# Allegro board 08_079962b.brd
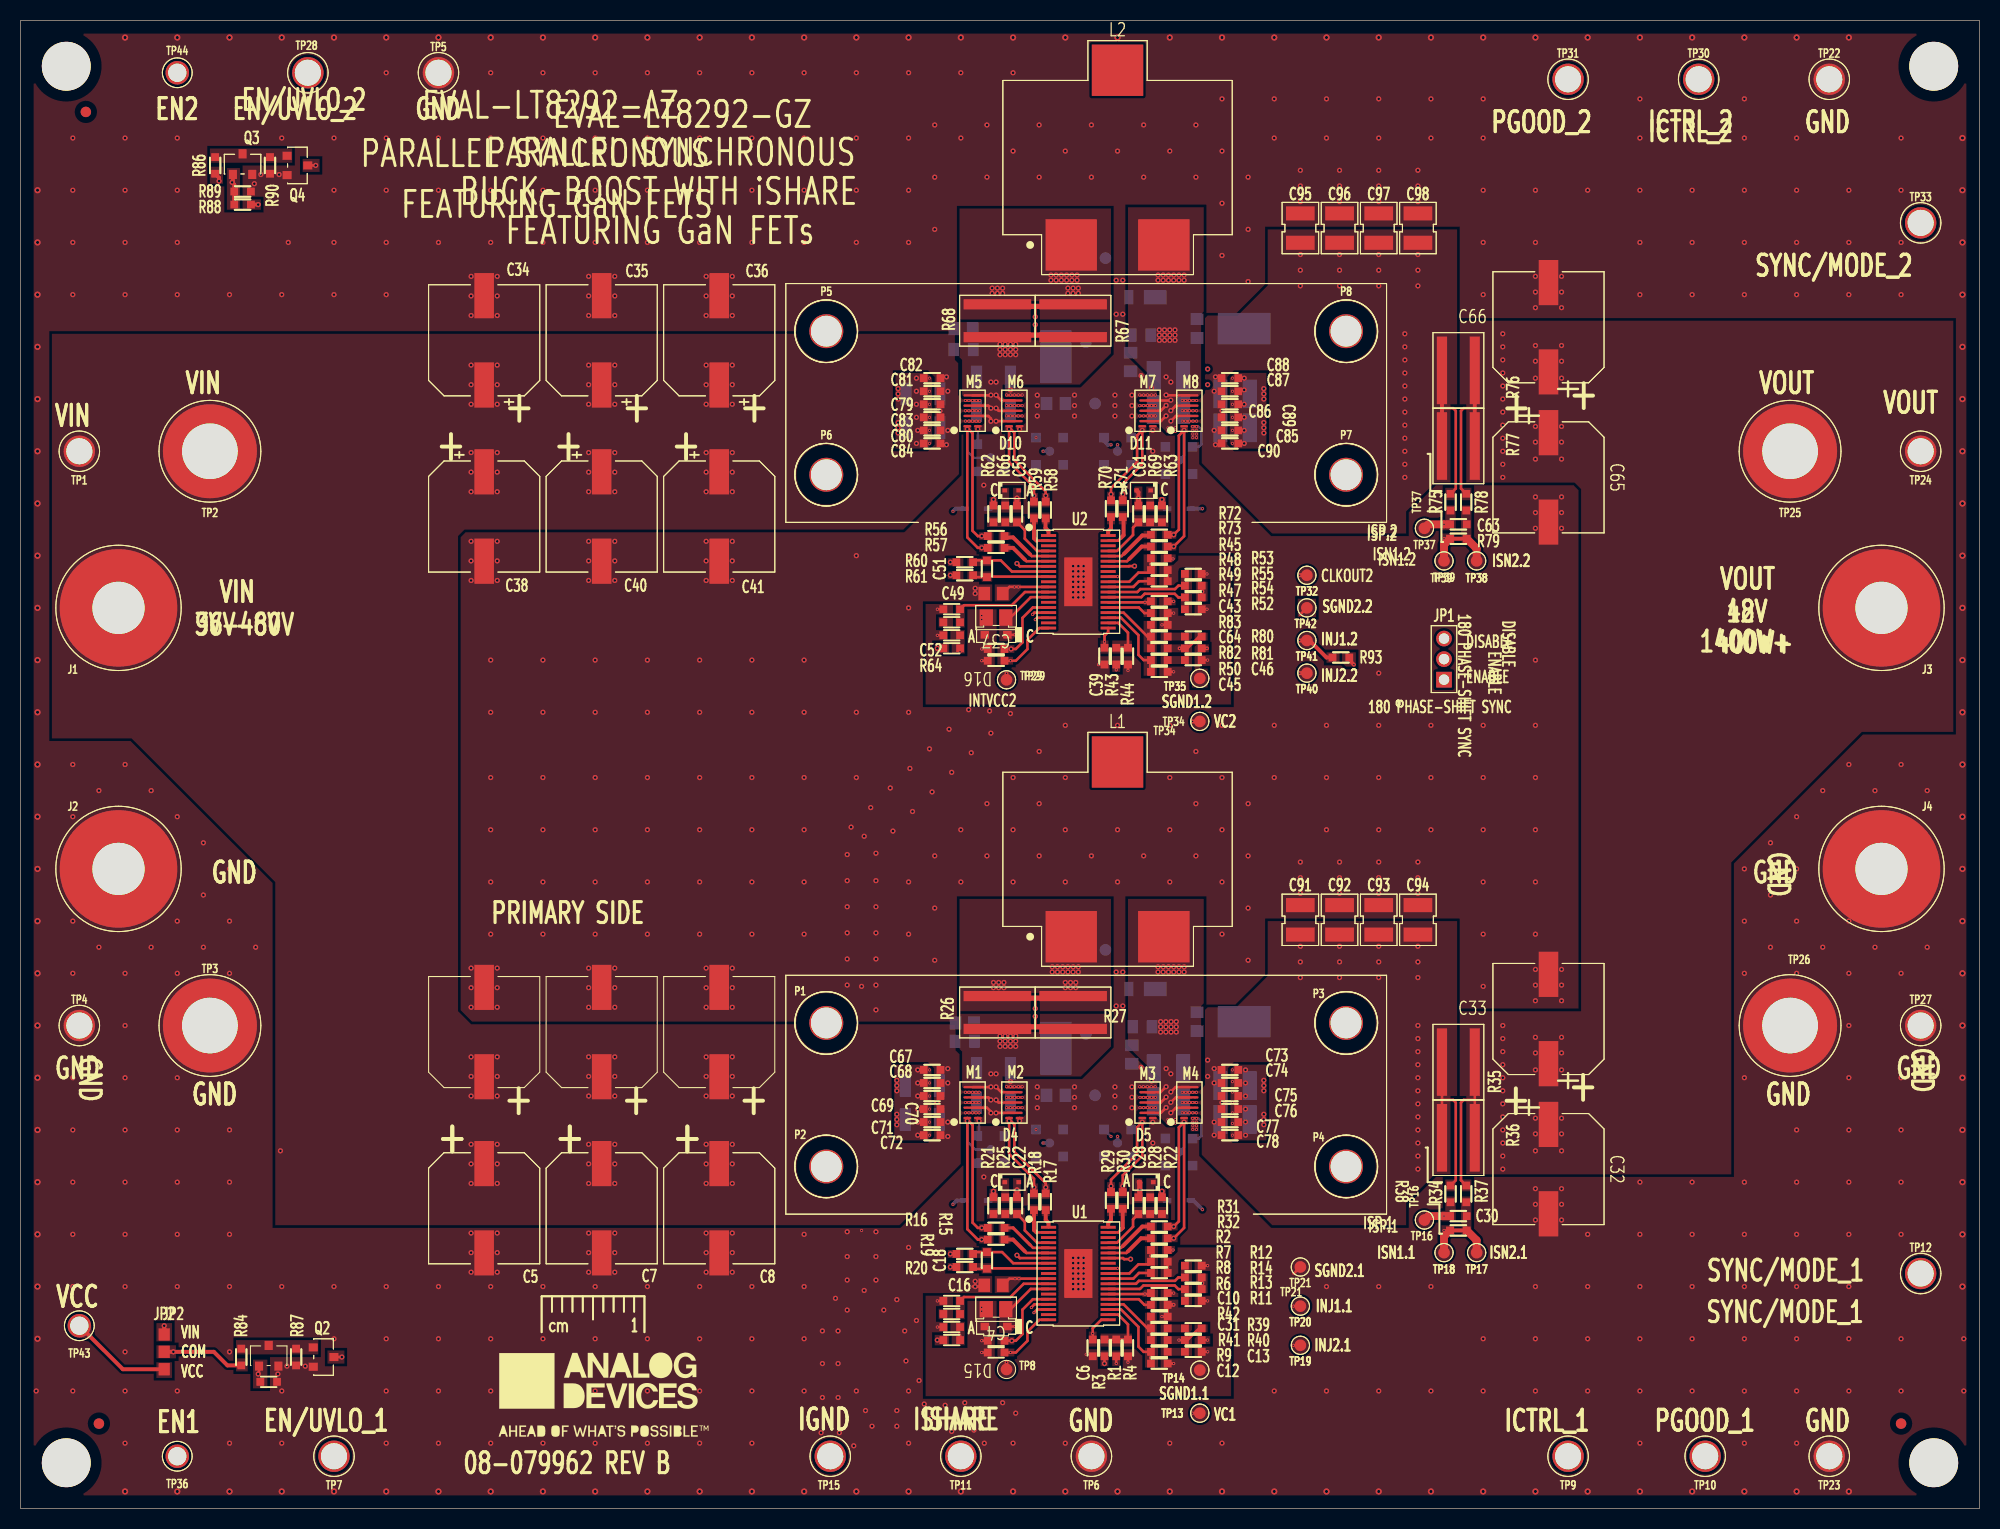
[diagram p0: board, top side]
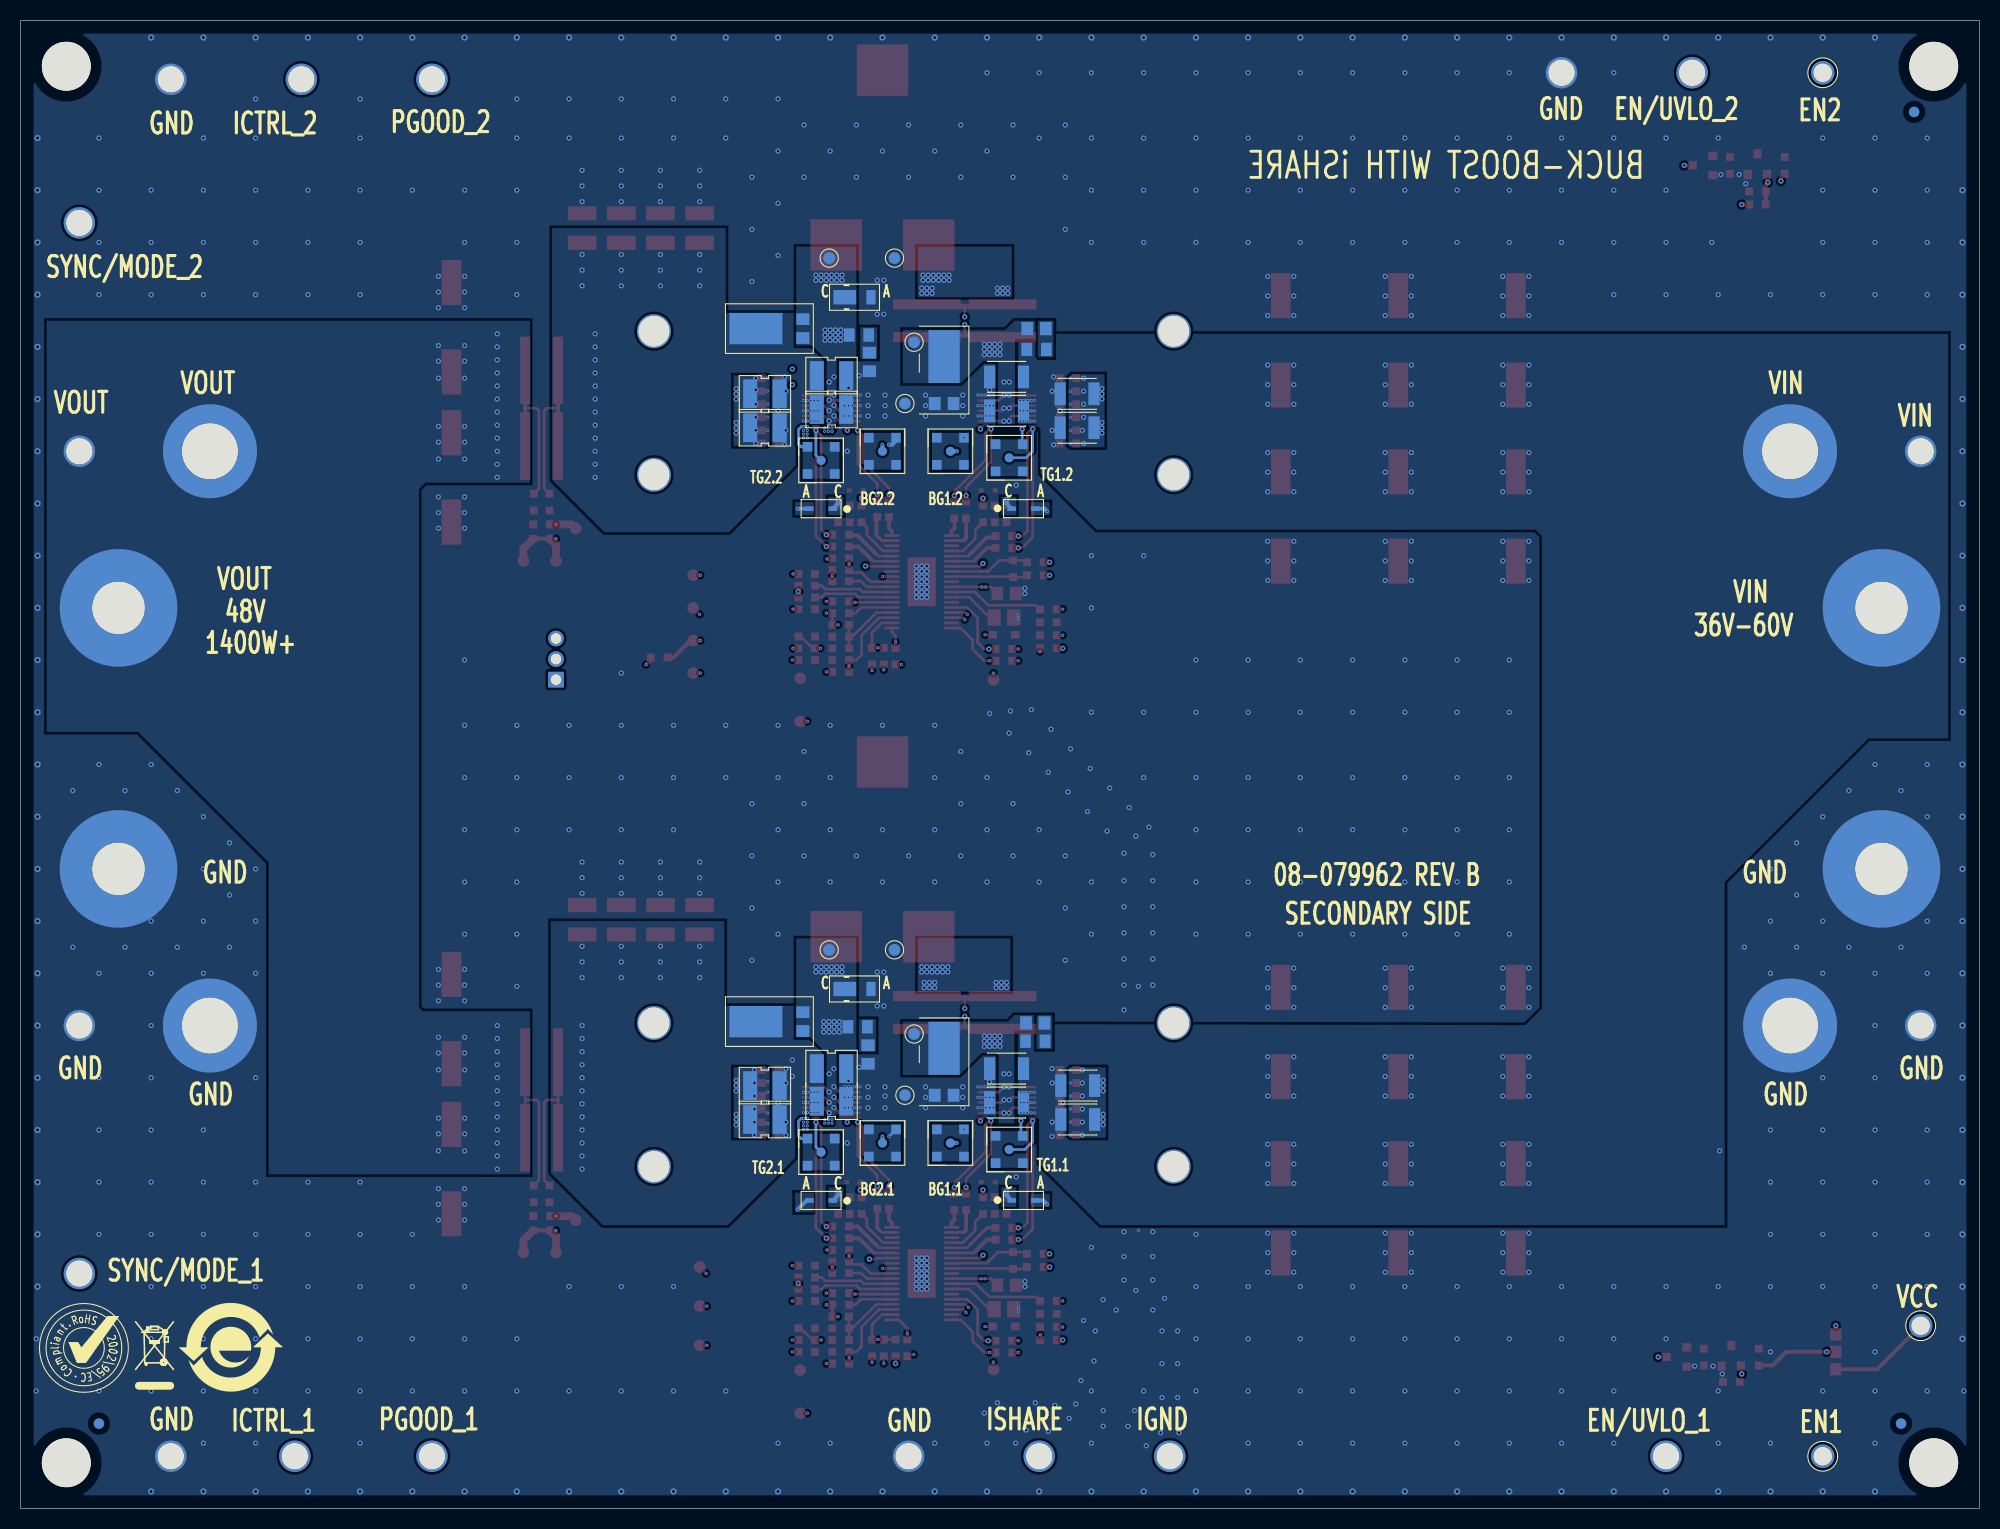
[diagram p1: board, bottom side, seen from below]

Outline 190.5 x 144.78 mm; copper layers: TOP, L2_GND, L3_SIG, L4_SIG, L5_GND, BOTTOM. Coordinates in mm from the lower left corner of the outline.
Outline path: 0,144.78 0,0 190.5,0 190.5,144.78 0,144.78

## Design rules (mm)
constraint set DEFAULT: min track width 0.254

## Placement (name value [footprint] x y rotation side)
C1  68UF  [CPLSMSQ406H500]  45.09 46.35 90 top
C2  68UF  [CPLSMSQ406H500]  56.52 46.35 90 top
C3  68UF  [CPLSMSQ406H500]  67.94 46.35 90 top
C4  10uF  [C0805H53]  94.87 19.38 180 top
C5  68UF  [CPLSMSQ406H500]  45.09 29.21 270 top
C6  TBD0603  [C0603]  104.27 15.62 270 top
C7  68UF  [CPLSMSQ406H500]  56.52 29.21 270 top
C8  68UF  [CPLSMSQ406H500]  67.94 29.21 270 top
C9  2200pF  [C0603]  90.55 20.19 0 top
C10  0.1uF  [C0603]  110.74 19.81 0 top
C11  4.7uF  [C1210H87]  94.62 39.5 0 bottom
C12  TBD0603  [C0603]  110.74 14.1 0 top
C13  6800PF  [C0603]  114.05 15.24 0 top
C14  4.7uF  [C1210H87]  94.62 42.8 0 bottom
C15  4.7uF  [C1210H87]  87.69 37.85 180 bottom
C16  1uF  [C0805]  94.62 21.72 180 top
C17  4.7uF  [C1210H87]  87.69 41.15 180 bottom
C18  1000pF  [C0603]  93.98 24.13 270 top
C19  1UF  [C0603]  94.87 16.32 180 top
C20  TBD0805  [C0805]  91.82 47.24 0 bottom
C21  10UF  [C1210H110]  111.63 42.8 180 bottom
C22  0.1uF  [C0603]  96.9 29.46 90 top
C23  10UF  [C1210H110]  111.63 39.62 180 bottom
C24  10UF  [C1210H110]  118.11 37.85 0 bottom
C25  10UF  [C1210H110]  118.11 41.15 0 bottom
C27  TBD0805  [C0805]  108.08 44.17 270 bottom
C28  0.1uF  [C0603]  108.71 29.46 90 top
C30  10uF  [C0603]  139.83 28.45 0 top
C31  TBD0603  [C0603]  110.74 17.53 180 top
C32  68UF  [CPLSMSQ406H500]  148.59 33.02 270 top
C33  68UF  [CPLSMSQ406H500]  148.59 47.62 90 top
C34  68UF  [CPLSMSQ406H500]  45.09 113.66 90 top
C35  68UF  [CPLSMSQ406H500]  56.52 113.66 90 top
C36  68UF  [CPLSMSQ406H500]  67.94 113.66 90 top
C37  10uF  [C0805H53]  94.87 86.69 180 top
C38  68UF  [CPLSMSQ406H500]  45.09 96.52 270 top
C39  TBD0603  [C0603]  105.41 82.93 270 top
C40  68UF  [CPLSMSQ406H500]  56.52 96.52 270 top
C41  68UF  [CPLSMSQ406H500]  67.94 96.52 270 top
C42  2200pF  [C0603]  90.55 87.5 0 top
C43  0.1uF  [C0603]  110.74 87.12 0 top
C44  4.7uF  [C1210H87]  94.62 110.11 0 bottom
C45  TBD0603  [C0603]  110.74 81.41 0 top
C46  6800PF  [C0603]  114.05 82.55 0 top
C47  4.7uF  [C1210H87]  87.76 108.46 180 bottom
C48  4.7uF  [C1210H87]  94.62 106.81 0 bottom
C49  1uF  [C0805]  94.62 89.03 180 top
C50  4.7uF  [C1210H87]  87.76 105.16 180 bottom
C51  1000pF  [C0603]  93.98 91.44 270 top
C52  1UF  [C0603]  94.87 83.63 180 top
C53  TBD0805  [C0805]  91.69 114.81 0 bottom
C54  10UF  [C1210H110]  111.63 106.93 180 bottom
C55  0.1uF  [C0603]  96.9 96.77 90 top
C56  10UF  [C1210H110]  111.63 110.24 180 bottom
C57  10UF  [C1210H110]  118.11 105.16 0 bottom
C58  10UF  [C1210H110]  118.11 108.46 0 bottom
C60  TBD0805  [C0805]  107.95 111.56 270 bottom
C61  0.1uF  [C0603]  108.71 96.77 90 top
C63  10uF  [C0603]  139.83 95.76 0 top
C64  TBD0603  [C0603]  110.74 84.84 180 top
C65  68UF  [CPLSMSQ406H500]  148.59 100.33 270 top
C66  68UF  [CPLSMSQ406H500]  148.59 114.94 90 top
C67  0.22UF  [C0603]  88.65 42.67 180 top
C68  0.22UF  [C0603]  88.65 41.4 180 top
C69  0.22UF  [C0603]  88.65 40.13 180 top
C70  0.22UF  [C0603]  88.65 38.86 180 top
C71  0.22UF  [C0603]  88.65 37.59 180 top
C72  0.22UF  [C0603]  88.65 36.32 180 top
C73  1UF  [C0603]  117.6 42.67 0 top
C74  1UF  [C0603]  117.6 41.4 0 top
C75  1UF  [C0603]  117.6 40.13 0 top
C76  1UF  [C0603]  117.6 38.86 0 top
C77  1UF  [C0603]  117.6 37.59 0 top
C78  1UF  [C0603]  117.6 36.32 0 top
C79  0.22UF  [C0603]  88.65 107.44 180 top
C80  0.22UF  [C0603]  88.65 104.9 180 top
C81  0.22UF  [C0603]  88.65 108.71 180 top
C82  0.22UF  [C0603]  88.65 109.98 180 top
C83  0.22UF  [C0603]  88.65 106.17 180 top
C84  0.22UF  [C0603]  88.65 103.63 180 top
C85  1UF  [C0603]  117.6 104.9 0 top
C86  1UF  [C0603]  117.6 106.17 0 top
C87  1UF  [C0603]  117.6 108.71 0 top
C88  1UF  [C0603]  117.6 109.98 0 top
C89  1UF  [C0603]  117.6 107.44 0 top
C90  1UF  [C0603]  117.6 103.63 0 top
C91  10UF  [C1210H110]  124.46 57.28 90 top
C92  10UF  [C1210H110]  128.27 57.28 90 top
C93  10UF  [C1210H110]  132.08 57.28 90 top
C94  10UF  [C1210H110]  135.89 57.28 90 top
C95  10UF  [C1210H110]  124.46 124.59 90 top
C96  10UF  [C1210H110]  128.27 124.59 90 top
C97  ZÁ  [C1210H110]  132.08 124.59 90 top
C98  10UF  [C1210H110]  135.89 124.59 90 top
D1  BAT46WJ,115  [SOD323F]  92.96 29.97 180 bottom
D2  BAT46WJ,115  [SOD323F]  112.65 29.97 0 bottom
D3  PDS3100-13  [POWERDI5]  100.69 43.46 180 bottom
D4  MM5Z5V1ST1G  [SOD523]  96.39 31.75 0 top
D5  MM5Z5V1ST1G  [SOD523]  109.47 31.75 180 top
D6  PDS3100-13  [POWERDI5]  117.68 47.37 90 bottom
D7  BAT46WJ,115  [SOD323F]  92.96 97.28 180 bottom
D8  BAT46WJ,115  [SOD323F]  112.65 97.28 0 bottom
D9  PDS3100-13  [POWERDI5]  100.69 110.77 180 bottom
D10  MM5Z5V1ST1G  [SOD523]  96.39 99.06 0 top
D11  MM5Z5V1ST1G  [SOD523]  109.22 99.06 180 top
D12  PDS3100-13  [POWERDI5]  117.68 114.81 90 bottom
D13  DFLS260-7  [POWERDI123]  109.4 50.55 180 bottom
D14  DFLS260-7  [POWERDI123]  109.4 117.86 180 bottom
D15  PLZ5V6A-G3/H  [DO219AC]  94.87 17.7 180 top
D16  PLZ5V6A-G3/H  [DO219AC]  94.87 85.01 180 top
J1  KFH-032-10ET  [CNPEMKFH-032]  9.53 87.63 0 top
J2  KFH-032-10ET  [CNPEMKFH-032]  9.53 62.23 0 top
J3  KFH-032-10ET  [CNPEMKFH-032]  180.97 87.63 0 top
J4  KFH-032-10ET  [CNPEMKFH-032]  180.97 62.23 0 top
J5  0734152063  [CNSMASQ136H203]  94.36 34.92 180 bottom
J6  0734152063  [CNSMASQ136H203]  100.08 35.56 180 bottom
J7  0734152063  [CNSMASQ136H203]  106.68 35.56 180 bottom
J8  0734152063  [CNSMASQ136H203]  112.65 34.67 180 bottom
J9  0734152063  [CNSMASQ136H203]  94.36 102.24 180 bottom
J10  0734152063  [CNSMASQ136H203]  100.08 102.87 180 bottom
J11  0734152063  [CNSMASQ136H203]  106.68 102.87 180 bottom
J12  0734152063  [CNSMASQ136H203]  112.65 101.98 180 bottom
JP1  TMM-103-02-L-S  [CNTHMHDR1X3L236W78H215]  138.43 80.65 90 top
JP2  3PINJUMPER0603  [JUMPER0603_3P]  13.97 15.24 90 top
L1  3.1UH  [LSML858W571H571]  106.68 64.13 0 top
L2  3.1UH  [LSML858W571H571]  106.68 131.44 0 top
M1  EPC2088  [DIE8_3_5X1_95_A]  92.58 39.5 90 top
M2  EPC2088  [DIE8_3_5X1_95_A]  96.65 39.5 90 top
M3  EPC2088  [DIE8_3_5X1_95_A]  109.6 39.5 90 top
M4  EPC2088  [DIE8_3_5X1_95_A]  113.66 39.5 90 top
M5  EPC2088  [DIE8_3_5X1_95_A]  92.58 106.81 90 top
M6  EPC2088  [DIE8_3_5X1_95_A]  96.65 106.81 90 top
M7  EPC2088  [DIE8_3_5X1_95_A]  109.6 106.81 90 top
M8  EPC2088  [DIE8_3_5X1_95_A]  113.66 106.81 90 top
NOREF  -  []  261.75 258.44 0 top
NOREF#2  -  []  10.29 147.7 0 top
NOREF#3  -  []  0 0 0 top
NOREF#4  -  []  190.5 0 90 top
NOREF#5  -  []  -34.73 322.66 0 top
NOREF#6  -  []  0 144.78 0 top
NOREF#7  -  []  -63.5 -69.85 0 top
NOREF#8  -  []  -209.55 -139.7 0 top
NOREF#9  -  []  190.5 0 90 top
NOREF#10  -  [unnamed#2]  6.35 135.89 0 top
NOREF#11  -  [unnamed#2]  4.45 4.45 180 top
NOREF#12  -  []  56.13 11.05 0 top
NOREF#13  VAL  []  103.63 107.57 0 top
NOREF#14  -  []  0 0 0 top
NOREF#15  -  [unnamed#2]  186.06 140.33 180 top
NOREF#16  -  []  0 0 0 top
NOREF#17  -  []  84.16 321.24 0 top
NOREF#18  -  []  -63.5 -69.85 0 top
NOREF#19  -  []  190.5 0 0 top
NOREF#20  -  []  4.45 4.45 0 top
NOREF#21  -  [unnamed#2]  186.06 4.45 180 top
NOREF#22  -  [unnamed#2]  4.45 140.33 180 top
NOREF#23  -  []  -53.12 239.13 0 top
NOREF#24  -  []  190.5 144.78 180 top
NOREF#25  -  []  -209.55 -139.7 0 top
NOREF#26  -  [unnamed#2]  182.88 8.26 0 top
NOREF#27  -  []  232.94 289.76 0 top
NOREF#28  -  [unnamed#2]  7.62 8.26 0 top
NOREF#29  -  []  102.62 150.37 0 top
NOREF#30  -  []  -63.5 -69.85 0 top
NOREF#31  -  []  50.67 17.14 0 top
NOREF#32  VAL  []  103.63 40.26 0 top
NOREF#33  -  []  4.45 4.45 0 top
NOREF#34  -  []  0 144.78 270 top
NOREF#35  -  []  70.89 219.1 0 top
NOREF#36  -  []  0 144.78 0 top
NOREF#37  -  [unnamed#2]  7.62 8.26 180 bottom
NOREF#38  -  []  184.34 15.62 180 bottom
NOREF#39  -  [unnamed#2]  182.88 8.26 180 bottom
NOREF#40  -  []  170.05 15.68 180 bottom
NOREF#41  -  [unnamed#2]  6.35 135.89 180 bottom
NOREF#42  -  []  177.67 11.62 180 bottom
P1  9774010243R  [CNWURTH9774010243R]  78.36 47.24 0 top
P2  9774010243R  [CNWURTH9774010243R]  78.36 33.27 0 top
P3  9774010243R  [CNWURTH9774010243R]  128.91 47.24 0 top
P4  9774010243R  [CNWURTH9774010243R]  128.91 33.27 0 top
P5  9774010243R  [CNWURTH9774010243R]  78.36 114.55 0 top
P6  9774010243R  [CNWURTH9774010243R]  78.36 100.58 0 top
P7  9774010243R  [CNWURTH9774010243R]  128.91 100.58 0 top
P8  9774010243R  [CNWURTH9774010243R]  128.91 114.55 0 top
Q1  BSS123-7-F  [SOT23-M3]  24.13 14.86 0 top
Q2  BSS123-7-F  [SOT23-M3]  29.46 14.73 270 top
Q3  BSS123-7-F  [SOT23-M3]  21.59 130.81 0 top
Q4  BSS123-7-F  [SOT23-M3]  26.92 130.68 270 top
R1  TBD0603  [R0603]  105.41 15.62 270 top
R2  TBD0603  [R0603]  110.74 25.15 180 top
R3  100K  [R0603]  106.55 15.62 90 top
R4  TBD0603  [R0603]  107.7 15.62 270 top
R5  18.7K  [R0603]  90.55 17.65 180 top
R6  100K  [R0603]  110.74 20.96 180 top
R7  TBD0603  [R0603]  110.74 24 0 top
R8  127K  [R0603]  110.74 22.91 0 top
R9  18.7K  [R0603]  110.74 15.24 0 top
R10  499K  [R0603]  90.55 16.38 0 top
R11  82K  [R0603]  114.05 20.19 0 top
R12  82K  [R0603]  114.05 23.62 0 top
R13  0  [R0603]  114.05 21.34 0 top
R14  0  [R0603]  114.05 22.48 0 top
R15  2  [R0603]  94.87 27.3 180 top
R16  1  [R0603]  94.87 26.16 180 top
R17  1  [R0603]  99.69 29.84 90 top
R18  2  [R0603]  98.55 29.84 90 top
R19  80.6  [R0603]  91.82 24.77 180 top
R20  80.6  [R0603]  91.82 23.5 180 top
R21  0  [R0603]  94.62 29.46 270 top
R22  0  [R0603]  111 29.46 270 top
R23  0  [R0603]  94.87 15.18 180 top
R24  TBD0805  [R0805]  91.82 45.47 180 bottom
R25  20  [R0603]  95.76 29.46 90 top
R26  0.003  [R1225H28]  95 48.26 90 top
R27  0.003  [R1225H28]  102.36 48.26 90 top
R28  20  [R0603]  109.85 29.46 90 top
R29  2  [R0603]  106.04 29.97 90 top
R30  1  [R0603]  107.19 29.97 90 top
R31  1  [R0603]  110.74 27.43 0 top
R32  2  [R0603]  110.74 26.29 0 top
R33  TBD0805  [R0805]  109.09 46.86 180 bottom
R34  49.9  [R0603]  139.06 30.61 270 top
R35  0.004  [R1225H28]  139.83 43.43 0 top
R36  0.004  [R1225H28]  139.83 36.07 0 top
R37  49.9  [R0603]  140.59 30.61 270 top
R38  TBD0603  [R0603]  139.83 27.05 0 top
R39  TBD0603  [R0603]  114.05 17.53 180 top
R40  0  [R0603]  114.05 16.38 180 top
R41  475K  [R0603]  110.74 16.38 180 top
R42  10K  [R0603]  110.74 18.67 0 top
R43  100K  [R0603]  106.55 82.93 90 top
R44  TBD0603  [R0603]  107.7 82.93 270 top
R45  TBD0603  [R0603]  110.74 92.46 180 top
R46  18.7K  [R0603]  90.55 84.96 180 top
R47  100K  [R0603]  110.74 88.26 180 top
R48  TBD0603  [R0603]  110.74 91.31 0 top
R49  127K  [R0603]  110.74 90.22 0 top
R50  18.7K  [R0603]  110.74 82.55 0 top
R51  499K  [R0603]  90.55 83.69 0 top
R52  82K  [R0603]  114.05 87.5 0 top
R53  82K  [R0603]  114.05 90.93 0 top
R54  0  [R0603]  114.05 88.65 0 top
R55  0  [R0603]  114.05 89.79 0 top
R56  2  [R0603]  94.87 94.62 180 top
R57  1  [R0603]  94.87 93.47 180 top
R58  1  [R0603]  99.69 97.16 90 top
R59  2  [R0603]  98.55 97.16 90 top
R60  80.6  [R0603]  91.82 92.07 180 top
R61  80.6  [R0603]  91.82 90.81 180 top
R62  0  [R0603]  94.62 96.77 270 top
R63  0  [R0603]  111 96.77 270 top
R64  TBD0603  [R0603]  94.87 82.49 180 top
R65  TBD0805  [R0805]  91.69 112.78 180 bottom
R66  20  [R0603]  95.76 96.77 90 top
R67  0.003  [R1225H28]  102.36 115.57 90 top
R68  0.003  [R1225H28]  95 115.57 90 top
R69  20  [R0603]  109.85 96.77 90 top
R70  2  [R0603]  106.04 97.28 90 top
R71  1  [R0603]  107.19 97.28 90 top
R72  1  [R0603]  110.74 94.74 0 top
R73  2  [R0603]  110.74 93.6 0 top
R74  TBD0805  [R0805]  108.97 114.17 180 bottom
R75  49.9  [R0603]  139.06 97.92 270 top
R76  0.004  [R1225H28]  139.83 110.74 0 top
R77  0.004  [R1225H28]  139.83 103.38 0 top
R78  49.9  [R0603]  140.59 97.92 270 top
R79  TBD0603  [R0603]  139.83 94.36 0 top
R80  TBD0603  [R0603]  114.05 84.84 180 top
R81  0  [R0603]  114.05 83.69 180 top
R82  475K  [R0603]  110.74 83.69 180 top
R83  10K  [R0603]  110.74 85.98 0 top
R84  TBD0603  [R0603]  21.46 14.73 90 top
R85  TBD0603  [R0603]  24.13 12.32 0 top
R86  TBD0603  [R0603]  18.92 130.68 90 top
R87  TBD0603  [R0603]  26.8 14.73 270 top
R88  TBD0603  [R0603]  21.59 126.87 180 top
R89  TBD0603  [R0603]  21.59 128.14 0 top
R90  TBD0603  [R0603]  24.26 130.68 270 top
R91  4.99K  [R0603]  90.55 18.92 0 top
R92  4.99K  [R0603]  90.55 86.23 0 top
R93  TBD0603  [R0603]  128.4 82.8 180 top
TP1  TESTPAD  [TPSMC40]  103.61 46.17 180 bottom
TP2  575-4  [CNBANANAD312LD203]  18.41 102.87 0 top
TP3  575-4  [CNBANANAD312LD203]  18.41 46.99 0 top
TP4  2501-2-00-80-00-00-07-0  [CNMILLMAX2501]  5.71 46.99 0 top
TP5  2501-2-00-80-00-00-07-0  [CNMILLMAX2501]  40.64 139.7 0 top
TP6  2501-2-00-80-00-00-07-0  [CNMILLMAX2501]  104.14 5.08 0 top
TP7  2501-2-00-80-00-00-07-0  [CNMILLMAX2501]  30.48 5.08 0 top
TP8  TESTPAD  [TPSMC40]  95.88 13.53 0 top
TP9  2501-2-00-80-00-00-07-0  [CNMILLMAX2501]  150.5 5.08 0 top
TP10  2501-2-00-80-00-00-07-0  [CNMILLMAX2501]  163.83 5.08 0 top
TP11  2501-2-00-80-00-00-07-0  [CNMILLMAX2501]  91.44 5.08 0 top
TP12  2501-2-00-80-00-00-07-0  [CNMILLMAX2501]  184.78 22.86 0 top
TP13  TESTPAD  [TPSMC40]  114.68 9.27 0 top
TP14  TESTPAD  [TPSMC40]  114.68 13.46 0 top
TP15  2501-2-00-80-00-00-07-0  [CNMILLMAX2501]  78.74 5.08 0 top
TP16  TESTPAD  [TPSMC40]  136.53 28.07 0 top
TP17  TESTPAD  [TPSMC40]  141.6 24.89 0 top
TP18  TESTPAD  [TPSMC40]  138.43 24.89 0 top
TP19  TESTPAD  [TPSMC40]  124.46 15.88 0 top
TP20  TESTPAD  [TPSMC40]  124.46 19.69 0 top
TP21  TESTPAD  [TPSMC40]  124.46 23.5 0 top
TP22  2501-2-00-80-00-00-07-0  [CNMILLMAX2501]  175.89 139.06 0 top
TP23  2501-2-00-80-00-00-07-0  [CNMILLMAX2501]  175.89 5.08 0 top
TP24  2501-2-00-80-00-00-07-0  [CNMILLMAX2501]  184.78 102.87 0 top
TP25  575-4  [CNBANANAD312LD203]  172.08 102.87 0 top
TP26  575-4  [CNBANANAD312LD203]  172.08 46.99 0 top
TP27  2501-2-00-80-00-00-07-0  [CNMILLMAX2501]  184.78 46.99 0 top
TP28  2501-2-00-80-00-00-07-0  [CNMILLMAX2501]  27.94 139.7 0 top
TP29  TESTPAD  [TPSMC40]  95.88 80.63 0 top
TP30  2501-2-00-80-00-00-07-0  [CNMILLMAX2501]  163.19 139.06 0 top
TP31  2501-2-00-80-00-00-07-0  [CNMILLMAX2501]  150.5 139.06 0 top
TP32  TESTPAD  [TPSMC40]  125.09 90.81 0 top
TP33  2501-2-00-80-00-00-07-0  [CNMILLMAX2501]  184.78 125.09 0 top
TP34  TESTPAD  [TPSMC40]  114.68 76.58 0 top
TP35  TESTPAD  [TPSMC40]  114.68 80.77 0 top
TP36  2308-2-00-44-00-00-07-0  [CNMILLMAX2308]  15.24 5.08 0 top
TP37  TESTPAD  [TPSMC40]  136.53 95.38 0 top
TP38  TESTPAD  [TPSMC40]  141.6 92.2 0 top
TP39  TESTPAD  [TPSMC40]  138.43 92.2 0 top
TP40  TESTPAD  [TPSMC40]  125.09 81.28 0 top
TP41  TESTPAD  [TPSMC40]  125.09 84.46 0 top
TP42  TESTPAD  [TPSMC40]  125.09 87.63 0 top
TP43  2308-2-00-44-00-00-07-0  [CNMILLMAX2308]  5.71 17.78 0 top
TP44  2308-2-00-44-00-00-07-0  [CNMILLMAX2308]  15.24 139.7 0 top
TP45  2501-2-00-80-00-00-07-0  [CNMILLMAX2501]  5.71 102.87 0 top
TP46  TESTPAD  [TPSMC40]  104.5 40.2 180 bottom
TP47  TESTPAD  [TPSMC40]  103.61 113.48 180 bottom
TP48  TESTPAD  [TPSMC40]  104.5 107.51 180 bottom
TP49  TESTPAD  [TPSMC40]  111.86 54.36 180 bottom
TP50  TESTPAD  [TPSMC40]  105.51 54.36 180 bottom
TP51  TESTPAD  [TPSMC40]  111.86 121.67 180 bottom
TP52  TESTPAD  [TPSMC40]  105.51 121.67 180 bottom
U1  LT8292AFE#PBF  [TSSOP38_PAD4_75X2_74_05-08-1772]  102.87 22.86 270 top
U2  LT8292AFE#PBF  [TSSOP38_PAD4_75X2_74_05-08-1772]  102.87 90.17 270 top

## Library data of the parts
C1-C3 C5 C7 C8 C32-C36 C38 C40 C41 C65 C66 = CAPP: Tolerance: 20; User Part Number: UPN; alternate symbols: (CPLSMSQ406H500); part number: CAPP_SM-68UF,80V,20,E042495,CPLSMSQ406H500; tolerance: 20
C4 C37 = CAP: Tolerance: 10; User Part Number: UPN; alternate symbols: (C0805H53); part number: CAP_SM-10UF,16V,10,E006166,C0805H53; tolerance: 10
C6 C12 C31 C39 C45 C64 = CAP: User Part Number: UPN; alternate symbols: (C0603); part number: CAP_SM-TBD0603,TBD0603,TBD0603,E000382,C0603
C9 C42 = CAP: Tolerance: 10; User Part Number: UPN; alternate symbols: (C0603); part number: CAP_SM-2200PF,50V,10,E028946,C0603; tolerance: 10
C10 C22 C28 C43 C55 C61 = CAP: Tolerance: 10; User Part Number: UPN; alternate symbols: (C0603); part number: CAP_SM-0.1UF,25V,10,E013746,C0603; tolerance: 10
C11 C14 C15 C17 C44 C47 C48 C50 = CAP: Tolerance: 10; User Part Number: UPN; alternate symbols: (C1210H87); part number: CAP_SM-4.7UF,100V,10,E033812,C1210H87; tolerance: 10
C13 C46 = CAP: Tolerance: 5; User Part Number: UPN; alternate symbols: (C0603); part number: CAP_SM-6800PF,50V,5,E071316,C0603; tolerance: 5
C16 C49 = CAP: User Part Number: UPN; Tolerance: 10; alternate symbols: (C0805); part number: CAP_SM-1UF,100V,10,E014208,C0805; tolerance: 10
C18 C51 = CAP: Tolerance: 5; User Part Number: UPN; alternate symbols: (C0603); part number: CAP_SM-1000PF,50V,5,E007908,C0603; tolerance: 5
C19 C52 C73-C78 C85-C90 = CAP: Tolerance: 10; User Part Number: UPN; alternate symbols: (C0603); part number: CAP_SM-1UF,100V,10,E068681,C0603; tolerance: 10
C20 C27 C53 C60 = CAP: User Part Number: UPN; alternate symbols: (C0805); part number: CAP_SM-TBD0805,TBD0805,TBD0805,E000383,C0805
C21 C23-C25 C54 C56-C58 C91-C98 = CAP: Tolerance: 10; User Part Number: UPN; alternate symbols: (C1210H110); part number: CAP_SM-10UF,100V,10,E067277,C1210H110; tolerance: 10
C30 C63 = CAP: Tolerance: 20; User Part Number: UPN; alternate symbols: (C0603); part number: CAP_SM-10UF,25V,20,E023693,C0603; tolerance: 20
C67-C72 C79-C84 = CAP: Tolerance: 10; User Part Number: UPN; alternate symbols: (C0603); part number: CAP_SM-0.22UF,100V,10,E061685,C0603; tolerance: 10
D1 D2 D7 D8 = DIOSCHOTTKY: Tolerance: N/A; User Part Number: UPN; alternate symbols: (SOD323F); part number: DIOSCHOTTKY_SM-BAT46WJ,115,100V,N/A,E016832,SOD323F; tolerance: N/A
D3 D6 D9 D12 = DIO3P_V7: Tolerance: N/A; User Part Number: UPN; alternate symbols: (POWERDI5); part number: DIO3P_V7_SM-PDS3100-13,100V,N/A,E042205,POWERDI5; tolerance: N/A
D4 D5 D10 D11 = DIOZNR: Tolerance: 2; User Part Number: UPN; alternate symbols: (SOD523); part number: DIOZNR_SM-MM5Z5V1ST1G,5.1V,2,E054247,SOD523; tolerance: 2
D13 D14 = DIOSCHOTTKY: User Part Number: UPN; Tolerance: N/A; alternate symbols: (POWERDI123); part number: DIOSCHOTTKY_SM-DFLS260-7,60V,N/A,E032987,POWERDI123; tolerance: N/A
D15 D16 = DIOZNR: User Part Number: UPN; Tolerance: 2.49; alternate symbols: (DO219AC); part number: DIOZNR_SM-PLZ5V6A-G3/H,5.42V,2.49,E071350,DO219AC; tolerance: 2.49
J1-J4 = CN1P: Tolerance: N/A; User Part Number: UPN; alternate symbols: (CNCFCKFH1032-10_C450D200); part number: CN1P_TH-KFH-032-10ET,E039893,CNPEMKFH-032; tolerance: N/A
J5-J12 = CNBNC5P: Tolerance: N/A; User Part Number: UPN; alternate symbols: (CNSMASQ136H203); part number: CNBNC5P_SM-0734152063,E050157,CNSMASQ136H203; tolerance: N/A
JP1 = CN3P: User Part Number: UPN; Tolerance: N/A; alternate symbols: (CNTHMHDR1X3L236W78H215); part number: CN3P_TH-TMM-103-02-L-S,E033760,CNTHMHDR1X3L236W78H215; tolerance: N/A
JP2 = NC3P_JMPR: Tolerance: N/A; User Part Number: UPN; alternate symbols: (JUMPER0603_3P); part number: NC3P_JMPR_SM-3PINJUMPER_0603,E031098,JUMPER0603_3P; tolerance: N/A
L1 L2 = IND: Tolerance: 15; User Part Number: UPN; alternate symbols: (LSML858W571H571); part number: IND_SM-3.1UH,15,E067382,LSML858W571H571; tolerance: 15
M1-M8 = TRANNGANFET8P: Tolerance: www.epc-co.com; User Part Number: UPN; alternate symbols: (DIE8_3_5X1_95_A); part number: TRANNGANFET8P_SM-EPC2088,E063004,DIE8_3_5X1_95_A; tolerance: www.epc-co.com
NOREF#13 = -: Tolerance: TOL; User Part Number: UPN
NOREF#32 = -: User Part Number: UPN; Tolerance: TOL
P1-P8 = CN1P: Tolerance: N/A; User Part Number: UPN; alternate symbols: (CNWURTH9774010243R); part number: CN1P_TH-9774010243R,E060235,CNWURTH9774010243R; tolerance: N/A
Q1-Q4 = TRANNMOSFET_V8: User Part Number: UPN; Tolerance: N/A; alternate symbols: (SOT23-M3); part number: TRANNMOSFET_V8_SM-BSS123-7-F,E072871,SOT23-M3; tolerance: N/A
R1 R2 R4 R7 R38 R39 R44 R45 R48 R64 R79 R80 R84-R90 R93 = RES: User Part Number: UPN; alternate symbols: (R0603); part number: RES_SM-TBD0603,E004050,TBD0603,TBD0603,R0603
R3 R6 R43 R47 = RES: Tolerance: 1; User Part Number: UPN; alternate symbols: (R0603); part number: RES_SM-100K,E010279,1/10W,1,R0603; tolerance: 1
R5 R9 R46 R50 = RES: Tolerance: 1; User Part Number: UPN; alternate symbols: (R0603); part number: RES_SM-18.7K,E011248,1/10W,1,R0603; tolerance: 1
R8 R49 = RES: Tolerance: 1; User Part Number: UPN; alternate symbols: (R0603); part number: RES_SM-127K,E039353,1/10W,1,R0603; tolerance: 1
R10 R51 = RES: Tolerance: 1; User Part Number: UPN; alternate symbols: (R0603); part number: RES_SM-499K,E015340,1/10W,1,R0603; tolerance: 1
R11 R12 R52 R53 = RES: Tolerance: 1; User Part Number: UPN; alternate symbols: (R0603); part number: RES_SM-82K,E068253,1/10W,1,R0603; tolerance: 1
R13 R14 R21-R23 R40 R54 R55 R62 R63 R81 = RES: Tolerance: JUMPER; User Part Number: UPN; alternate symbols: (R0603); part number: RES_SM-0,E006826,1/10W,JUMPER,R0603; tolerance: JUMPER
R15 R18 R29 R32 R56 R59 R70 R73 = RES: Tolerance: 5; User Part Number: UPN; alternate symbols: (R0603); part number: RES_SM-2,E026235,1/10W,5,R0603; tolerance: 5
R16 R17 R30 R31 R57 R58 R71 R72 = RES: Tolerance: 5; User Part Number: UPN; alternate symbols: (R0603); part number: RES_SM-1,E011738,1/10W,5,R0603; tolerance: 5
R19 R20 R60 R61 = RES: Tolerance: 1; User Part Number: UPN; alternate symbols: (R0603); part number: RES_SM-80.6,E003675,1/10W,1,R0603; tolerance: 1
R24 R33 R65 R74 = RES: User Part Number: UPN; alternate symbols: (R0805); part number: RES_SM-TBD0805,E004051,TBD0805,TBD0805,R0805
R25 R28 R66 R69 = RES: Tolerance: 1; User Part Number: UPN; alternate symbols: (R0603); part number: RES_SM-20,E032358,1/10W,1,R0603; tolerance: 1
R26 R27 R67 R68 = RES: User Part Number: UPN; Tolerance: 1; alternate symbols: (R1225H28); part number: RES_SM-0.003,E050854,3W,1,R1225H28; tolerance: 1
R34 R37 R75 R78 = RES: Tolerance: 1; User Part Number: UPN; alternate symbols: (R0603); part number: RES_SM-49.9,E003673,1/10W,1,R0603; tolerance: 1
R35 R36 R76 R77 = RES: User Part Number: UPN; Tolerance: 1; alternate symbols: (R1225H28); part number: RES_SM-0.004,E047477,3W,1,R1225H28; tolerance: 1
R41 R82 = RES: Tolerance: 1; User Part Number: UPN; alternate symbols: (R0603); part number: RES_SM-475K,E032846,1/10W,1,R0603; tolerance: 1
R42 R83 = RES: Tolerance: 1; User Part Number: UPN; alternate symbols: (R0603); part number: RES_SM-10K,E003671,1/10W,1,R0603; tolerance: 1
R91 R92 = RES: Tolerance: 1; User Part Number: UPN; alternate symbols: (R0603); part number: RES_SM-4.99K,E003726,1/10W,1,R0603; tolerance: 1
TP1 TP8 TP13 TP14 TP16-TP21 TP29 TP32 TP34 TP35 TP37-TP42 TP46-TP52 = NCTESTPAD: Tolerance: N/A; User Part Number: UPN; alternate symbols: (TPSMC40); part number: NCTESTPAD_SM-TESTPAD,E019801,TPSMC40; tolerance: N/A
TP2 TP3 TP25 TP26 = CNTP1P: Tolerance: N/A; User Part Number: UPN; alternate symbols: (CNBANANAD312LD203); part number: CNTP1P_TH-575-4,E012555,CNBANANAD312LD203; tolerance: N/A
TP4-TP7 TP9-TP12 TP15 TP22-TP24 TP27 TP28 TP30 TP31 TP33 TP45 = CNTP1P: User Part Number: UPN; Tolerance: N/A; alternate symbols: (CNMILLMAX2501); part number: CNTP1P_TH-2501-2-00-80-00-00-07-0,E031108,CNMILLMAX2501; tolerance: N/A
TP36 TP43 TP44 = CNTP1P: User Part Number: UPN; Tolerance: N/A; alternate symbols: (CNMILLMAX2308); part number: CNTP1P_TH-2308-2-00-44-00-00-07-0,E063743,CNMILLMAX2308; tolerance: N/A
U1 U2 = ADLT8292: User Part Number: UPN; Tolerance: N/A; alternate symbols: (TSSOP38_PAD4_75X2_74_05-08-1772); part number: ADLT8292_SM-LT8292AFE#PBF,E062951,TSSOP38_PAD4_75X2_74_05-08-1772; tolerance: N/A

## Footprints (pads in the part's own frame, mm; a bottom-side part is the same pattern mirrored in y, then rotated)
C0603
  rect 0.762x0.762 smd: 1(-0.813,0) 2(0.813,0)
C0805
  rect 1.143x1.295 smd: 1(-0.9,0) 2(0.9,0)
C0805H53
  rect 1.295x1.6 smd: 1(-0.953,0) 2(0.953,0)
C1210H87
  rect 1.092x2.21 smd: 1(-1.646,0) 2(1.646,0)
C1210H110
  rect 1.372x2.794 smd: 1(-1.431,0) 2(1.431,0)
CNBANANAD312LD203
  round 9.144 hole 5.41: 1(0,0)
CNMILLMAX2308
  round 2.286 hole 1.778: 1(0,0)
CNMILLMAX2501
  round 3.048 hole 2.54: 1(0,0)
CNPEMKFH-032
  round 11.43 hole 5.08: 1(0,0)
CNSMASQ136H203
  round 0.889 smd: 1(0,0)
  rect 0.94x0.94 smd: 2(-1.32,-1.32) 3(1.32,-1.32) 4(1.32,1.32) 5(-1.32,1.32)
CNTHMHDR1X3L236W78H215
  rect 1.524x1.524 hole 1.016: 1(0,0)
  round 1.524 hole 1.016: 2(2,0) 3(4,0)
CNWURTH9774010243R
  round 3.302 hole 2.997 unplated: (0,0)
  round 0 smd: 1(0,0)
CPLSMSQ406H500
  rect 4.394x1.905 smd: N(4.347,0) P(-4.347,0)
DIE8_3_5X1_95_A
  oval 0.229x0.762 smd: 1(-1.5,0.513) 2(-1.5,-0.513)
  oval 0.229x1.6 smd: 3(-1,0) 5(0,0) 7(1,0)
  oval 0.229x1.778 smd: 4(-0.5,0) 6(0.5,0) 8(1.5,0)
DO219AC
  rect 0.838x0.737 smd: A(1.1,0) C(-1.1,0)
JUMPER0603_3P
  rect 1.194x1.092 smd: 1(-1.694,0) 2(0,0) 3(1.694,0)
LSML858W571H571
  rect 5.004x5.004 smd: (0,8.502) 1(-4.502,-8.502) 2(4.502,-8.502)
POWERDI5
  rect 1.143x1.27 smd: 1(-0.92,-3.255) 2(0.92,-3.255)
  rect 3.048x5.156 smd: 3(0,1.312)
POWERDI123
  rect 0.889x1.397 smd: A(1.606,0)
  rect 2.21x1.397 smd: C(-0.945,0)
R0603
  rect 0.762x0.762 smd: 1(-0.813,0) 2(0.813,0)
R0805
  rect 1.041x1.295 smd: 1(-0.95,0) 2(0.95,0)
R1225H28
  rect 0.991x6.579 smd: 1(-1.595,0) 2(1.595,0)
SOD323F
  rect 0.838x0.457 smd: A(1.14,0) C(-1.14,0)
SOD523
  rect 0.457x0.406 smd: A(0.679,0) C(-0.679,0)
SOT23-M3
  rect 0.787x0.889 smd: 1(-0.94,-1.003) 2(0.94,-1.003) 3(0,1.003)
TPSMC40
  round 1.143 smd: 1(0,0)
TSSOP38_PAD4_75X2_74_05-08-1772
  rect 0.279x1.473 smd: 1(-4.5,-2.9) 2(-4,-2.9) 3(-3.5,-2.9) 4(-3,-2.9) 5(-2.5,-2.9) 6(-2,-2.9) 7(-1.5,-2.9) 8(-1,-2.9) 9(-0.5,-2.9) 10(0,-2.9) 11(0.5,-2.9) 12(1,-2.9) 13(1.5,-2.9) 14(2,-2.9) 15(2.5,-2.9) 16(3,-2.9) 17(3.5,-2.9) 18(4,-2.9) 19(4.5,-2.9) 20(4.5,2.9) 21(4,2.9) 22(3.5,2.9) 23(3,2.9) 24(2.5,2.9) 25(2,2.9) 26(1.5,2.9) 27(1,2.9) 28(0.5,2.9) 29(0,2.9) 30(-0.5,2.9) 31(-1,2.9) 32(-1.5,2.9) 33(-2,2.9) 34(-2.5,2.9) 35(-3,2.9) 36(-3.5,2.9) 37(-4,2.9) 38(-4.5,2.9)
  rect 4.75x2.743 smd: 39(0,0)
unnamed#2
  round 1.016 smd: (0,0)

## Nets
GND_SIGNAL: C1.N(N2) C2.N(N2) C3.N(N2) C4.2(N2) C5.N(N2) C6.2(N2) C7.N(N2) C8.N(N2) C9.1 C10.2(N2) C11.2(N2) C12.2(N2) C13.2(N2) C14.2(N2) C15.2(N2) C16.2(N2) C17.2(N2) C19.2(N2) C21.2(N2) C23.2(N2) C24.2(N2) C25.2(N2) C27.2(N2) C32.N(N2) C33.N(N2) C34.N(N2) C35.N(N2) C36.N(N2) C37.2(N2) C38.N(N2) C39.2(N2) C40.N(N2) C41.N(N2) C42.1 C43.2(N2) C44.2(N2) C45.2(N2) C46.2(N2) C47.2(N2) C48.2(N2) C49.2(N2) C50.2(N2) C52.2(N2) C54.2(N2) C56.2(N2) C57.2(N2) C58.2(N2) C60.2(N2) C65.N(N2) C66.N(N2) C67.2(N2) C68.2(N2) C69.2(N2) C70.2(N2) C71.2(N2) C72.2(N2) C73.2(N2) C74.2(N2) C75.2(N2) C76.2(N2) C77.2(N2) C78.2(N2) C79.2(N2) C80.2(N2) C81.2(N2) C82.2(N2) C83.2(N2) C84.2(N2) C85.2(N2) C86.2(N2) C87.2(N2) C88.2(N2) C89.2(N2) C90.2(N2) C91.2(N2) C92.2(N2) C93.2(N2) C94.2(N2) C95.2(N2) C96.2(N2) C97.2(N2) C98.2(N2) D3.1 D3.2 D9.1 D9.2 D13.A(P) D14.A(P) D15.A(P) D16.A(P) J2.1(N1) J4.1(N1) J6.2 J6.3 J6.4 J6.5(SH4) J7.2 J7.3 J7.4 J7.5(SH4) J10.2 J10.3 J10.4 J10.5(SH4) J11.2 J11.3 J11.4 J11.5(SH4) M2.2 M2.4 M2.6 M2.8(S4) M3.2 M3.4 M3.6 M3.8(S4) M6.2 M6.4 M6.6 M6.8(S4) M7.2 M7.4 M7.6 M7.8(S4) Q1.2(S) Q2.2(S) Q3.2(S) Q4.2(S) R4.2(N2) R5.2(N2) R7.2(N2) R8.2(N2) R11.2(N2) R12.2(N2) R23.2(N2) R42.2(N2) R44.2(N2) R46.2(N2) R48.2(N2) R49.2(N2) R52.2(N2) R53.2(N2) R64.2(N2) R83.2(N2) R85.2(N2) R87.2(N2) R89.2(N2) R90.2(N2) TP3.1(N1) TP4.1(N1) TP5.1(N1) TP6.1(N1) TP14.1(N1) TP21.1(N1) TP22.1(N1) TP23.1(N1) TP26.1(N1) TP27.1(N1) TP35.1(N1) TP42.1(N1) TP46.1(N1) TP48.1(N1) TP50.1(N1) TP52.1(N1) U1.39 U2.39
VIN: C1.P C2.P C3.P C5.P C7.P C8.P C11.1 C14.1 C15.1 C16.1 C17.1 C34.P C35.P C36.P C38.P C40.P C41.P C44.1 C47.1 C48.1 C49.1 C50.1 C67.1 C68.1 C69.1 C70.1 C71.1 C72.1 C79.1 C80.1 C81.1 C82.1 C83.1 C84.1 J1.1(N1) JP2.3 M1.3 M1.5 M1.7 M5.3 M5.5 M5.7 R10.1 R24.1 R51.1 R65.1 TP2.1(N1) TP45.1(N1) U1.11 U2.11
CLKOUT1: JP1.2 U1.30
EN1: Q1.1 R85.1 R88.1 TP36.1(N1)
EN/UVLO_1: Q2.3 R5.1 R10.2(N2) R91.1 TP7.1(N1)
EN/UVLO_2: Q4.3 R46.1 R51.2(N2) R92.1 TP28.1(N1)
ICTRL_2: R1.2(N2) R43.2(N2) R44.1 TP30.1(N1) U2.21
IGND: R23.1 R64.1 TP15.1(N1) U1.19 U2.19
INJ1.1: R39.1 R40.2(N2) R41.1 R93.1 TP20.1(N1)
INTVCC1: C4.1 D1.A(P) D2.A(P) D15.C R2.1 R3.1 R6.1 R13.2(N2) R14.2(N2) TP8.1(N1) U1.13
INTVCC2: C37.1 D7.A(P) D8.A(P) D16.C R43.1 R45.1 R47.1 R54.2(N2) R55.2(N2) TP29.1(N1) U2.13
ISHARE: C6.1 C39.1 TP11.1(N1) U1.20 U2.20
OUT: C32.P C33.P C65.P C66.P J3.1(N1) R35.2(N2) R36.2(N2) R37.1 R40.1 R76.2(N2) R77.2(N2) R78.1 R81.1 TP19.1(N1) TP24.1(N1) TP25.1(N1) TP40.1(N1)
PGOOD1: R6.2(N2) TP10.1(N1) U1.25
PGOOD2: R47.2(N2) TP31.1(N1) U2.25
UNNAMED_1_ADLT8292_I154_BG1N: R18.1 U1.2
UNNAMED_1_ADLT8292_I154_BG1P: R17.1 U1.1
UNNAMED_1_ADLT8292_I154_BG2N: R30.1 U1.37
UNNAMED_1_ADLT8292_I154_BG2P: R29.1 U1.38
UNNAMED_1_ADLT8292_I154_BST1: C22.1 R21.2(N2) R25.1 U1.4
UNNAMED_1_ADLT8292_I154_BST2: C28.1 R22.2(N2) R28.1 U1.35
UNNAMED_1_ADLT8292_I154_EN: C9.2(N2) R91.2(N2) U1.12
UNNAMED_1_ADLT8292_I154_ICTRL: R1.1 R3.2(N2) R4.1 TP9.1(N1) U1.21
UNNAMED_1_ADLT8292_I154_ISN: C30.2(N2) R37.2(N2) R38.1 R38.2(N2) TP17.1(N1) TP18.1(N1) U1.17
UNNAMED_1_ADLT8292_I154_LSN: C18.2(N2) R20.1 U1.9
UNNAMED_1_ADLT8292_I154_LSP: C18.1 R19.1 U1.8
UNNAMED_1_ADLT8292_I154_RDT1: R11.1 R13.1 U1.26
UNNAMED_1_ADLT8292_I154_RDT2: R12.1 R14.1 U1.27
UNNAMED_1_ADLT8292_I154_RT: R8.1 U1.28
UNNAMED_1_ADLT8292_I154_SS: C10.1 U1.24
UNNAMED_1_ADLT8292_I154_SW1: C20.2(N2) C22.2(N2) D3.3(C) D4.A(P) J5.2 J5.3 J5.4 J5.5(SH4) M1.2 M1.4 M1.6 M1.8(S4) M2.3 M2.5 M2.7 R19.2(N2) R26.1 R27.1 TP1.1(N1) U1.7
UNNAMED_1_ADLT8292_I154_SW2: C28.2(N2) D5.A(P) D6.1 D6.2 D13.C J8.2 J8.3 J8.4 J8.5(SH4) L1.2(N2) M3.3 M3.5 M3.7 M4.2 M4.4 M4.6 M4.8(S4) R33.1 TP49.1(N1) U1.32
UNNAMED_1_ADLT8292_I154_SYNC: R2.2(N2) R7.1 TP12.1(N1) U1.29
UNNAMED_1_ADLT8292_I154_TG1N: R16.1 U1.6
UNNAMED_1_ADLT8292_I154_TG1P: R15.1 U1.5
UNNAMED_1_ADLT8292_I154_TG2N: R32.1 U1.33
UNNAMED_1_ADLT8292_I154_TG2P: R31.1 U1.34
UNNAMED_1_ADLT8292_I154_VC: C12.1 R9.1 TP13.1(N1) U1.22
UNNAMED_1_ADLT8292_I154_VOUT: C19.1 C21.1 C23.1 C24.1 C25.1 C73.1 C74.1 C75.1 C76.1 C77.1 C78.1 C91.1 C92.1 C93.1 C94.1 D6.3(C) M4.3 M4.5 M4.7 R34.1 R35.1 R36.1 U1.15(VOUT)
UNNAMED_1_CAP_I52_N1: C31.1 R39.2(N2)
UNNAMED_1_CAP_I52_N2: C31.2(N2) R41.2(N2) R42.1 U1.23
UNNAMED_1_CAP_I61_N1: C30.1 R34.2(N2) TP16.1(N1) U1.16
UNNAMED_1_CAP_I80_N1: C27.1 R33.2(N2)
UNNAMED_1_CAP_I93_N1: C20.1 R24.2(N2)
UNNAMED_1_CAP_I158_N1: C13.1 R9.2(N2)
UNNAMED_1_CNBNC5P_I74_CNTR: J8.1 M4.1 R31.2(N2) R32.2(N2)
UNNAMED_1_CNBNC5P_I82_CNTR: J7.1 M3.1 R29.2(N2) R30.2(N2)
UNNAMED_1_CNBNC5P_I107_CNTR: J5.1 M1.1 R15.2(N2) R16.2(N2)
UNNAMED_1_CNBNC5P_I114_CNTR: J6.1 M2.1 R17.2(N2) R18.2(N2)
UNNAMED_1_CNTP1P_I232_N1: JP2.1 TP43.1(N1)
UNNAMED_1_DIOSCHOTTKY_I102_N: D2.C R22.1
UNNAMED_1_DIOSCHOTTKY_I103_N: D1.C R21.1
UNNAMED_1_DIOZNR_I191_N: D4.C R25.2(N2)
UNNAMED_1_DIOZNR_I193_N: D5.C R28.2(N2)
UNNAMED_1_IND_I264_N1: L1.1 R20.2(N2) R26.2(N2) R27.2(N2)
UNNAMED_1_RES_I231_N1: Q1.3 Q2.1 R84.2(N2) R87.1
UNNAMED_1_RES_I241_N1: Q3.3 Q4.1 R86.2(N2) R90.1
UNNAMED_1_RES_I248_N1: Q3.1 R88.2(N2) R89.1 TP44.1(N1)
UNNAMED_1_RES_I252_N1: JP2.2(COM) R84.1 R86.1
UNNAMED_3_ADLT8292_I52_BG1N: R59.1 U2.2
UNNAMED_3_ADLT8292_I52_BG1P: R58.1 U2.1
UNNAMED_3_ADLT8292_I52_BG2N: R71.1 U2.37
UNNAMED_3_ADLT8292_I52_BG2P: R70.1 U2.38
UNNAMED_3_ADLT8292_I52_BST1: C55.1 R62.2(N2) R66.1 U2.4
UNNAMED_3_ADLT8292_I52_BST2: C61.1 R63.2(N2) R69.1 U2.35
UNNAMED_3_ADLT8292_I52_CLKOUT: TP32.1(N1) U2.30
UNNAMED_3_ADLT8292_I52_EN: C42.2(N2) R92.2(N2) U2.12
UNNAMED_3_ADLT8292_I52_FB: C64.2(N2) R82.2(N2) R83.1 U2.23
UNNAMED_3_ADLT8292_I52_ISN: C63.2(N2) R78.2(N2) R79.1 R79.2(N2) TP38.1(N1) TP39.1(N1) U2.17
UNNAMED_3_ADLT8292_I52_ISP: C63.1 R75.2(N2) TP37.1(N1) U2.16
UNNAMED_3_ADLT8292_I52_LSN: C51.2(N2) R61.1 U2.9
UNNAMED_3_ADLT8292_I52_LSP: C51.1 R60.1 U2.8
UNNAMED_3_ADLT8292_I52_RDT1: R52.1 R54.1 U2.26
UNNAMED_3_ADLT8292_I52_RDT2: R53.1 R55.1 U2.27
UNNAMED_3_ADLT8292_I52_RT: R49.1 U2.28
UNNAMED_3_ADLT8292_I52_SS: C43.1 U2.24
UNNAMED_3_ADLT8292_I52_SW1: C53.2(N2) C55.2(N2) D9.3(C) D10.A(P) J9.2 J9.3 J9.4 J9.5(SH4) M5.2 M5.4 M5.6 M5.8(S4) M6.3 M6.5 M6.7 R60.2(N2) R67.1 R68.1 TP47.1(N1) U2.7
UNNAMED_3_ADLT8292_I52_SW2: C61.2(N2) D11.A(P) D12.1 D12.2 D14.C J12.2 J12.3 J12.4 J12.5(SH4) L2.2(N2) M7.3 M7.5 M7.7 M8.2 M8.4 M8.6 M8.8(S4) R74.1 TP51.1(N1) U2.32
UNNAMED_3_ADLT8292_I52_SYNC: JP1.1 R45.2(N2) R48.1 TP33.1(N1) U2.29
UNNAMED_3_ADLT8292_I52_TG1N: R57.1 U2.6
UNNAMED_3_ADLT8292_I52_TG1P: R56.1 U2.5
UNNAMED_3_ADLT8292_I52_TG2N: R73.1 U2.33
UNNAMED_3_ADLT8292_I52_TG2P: R72.1 U2.34
UNNAMED_3_ADLT8292_I52_VC: C45.1 R50.1 TP34.1(N1) U2.22
UNNAMED_3_ADLT8292_I52_VOUT: C52.1 C54.1 C56.1 C57.1 C58.1 C85.1 C86.1 C87.1 C88.1 C89.1 C90.1 C95.1 C96.1 C97.1 C98.1 D12.3(C) M8.3 M8.5 M8.7 R75.1 R76.1 R77.1 U2.15(VOUT)
UNNAMED_3_CAP_I32_N1: C46.1 R50.2(N2)
UNNAMED_3_CAP_I75_N1: C53.1 R65.2(N2)
UNNAMED_3_CAP_I110_N1: C60.1 R74.2(N2)
UNNAMED_3_CAP_I128_N1: C64.1 R80.2(N2)
UNNAMED_3_CNBNC5P_I67_CNTR: J10.1 M6.1 R58.2(N2) R59.2(N2)
UNNAMED_3_CNBNC5P_I68_CNTR: J9.1 M5.1 R56.2(N2) R57.2(N2)
UNNAMED_3_CNBNC5P_I117_CNTR: J11.1 M7.1 R70.2(N2) R71.2(N2)
UNNAMED_3_CNBNC5P_I123_CNTR: J12.1 M8.1 R72.2(N2) R73.2(N2)
UNNAMED_3_DIOSCHOTTKY_I96_N: D7.C R62.1
UNNAMED_3_DIOSCHOTTKY_I97_N: D8.C R63.1
UNNAMED_3_DIOZNR_I108_N: D10.C R66.2(N2)
UNNAMED_3_DIOZNR_I113_N: D11.C R69.2(N2)
UNNAMED_3_IND_I196_N1: L2.1 R61.2(N2) R67.2(N2) R68.2(N2)
UNNAMED_3_NCTESTPAD_I137_N1: R80.1 R81.2(N2) R82.1 R93.2(N2) TP41.1(N1)

Pads without a net: JP1 3; P1 1; P2 1; P3 1; P4 1; P5 1; P6 1; P7 1; P8 1; U1 3 10 14 18 31 36; U2 3 10 14 18 31 36

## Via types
v1: diameter 0.508, hole 0.254, TOP to BOTTOM, 1157 vias
v2: diameter 0.305, hole 0.152, TOP to BOTTOM, 268 vias
v3: diameter 0.61, hole 0.305, TOP to BOTTOM, 114 vias

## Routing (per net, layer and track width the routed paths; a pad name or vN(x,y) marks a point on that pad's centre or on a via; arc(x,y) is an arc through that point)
GND_SIGNAL: length 68.9
  TOP w0.254: R11.2 v2(115.44,20.19) ; v2(109.6,106.31) v2(109.98,106.31) v2(110.36,106.31) ; R48.2 v2(111.56,90.77) R49.2 ; v2(109.6,107.31) v2(109.98,107.31) v2(110.36,107.31) ; v2(111,18.67) R42.2 C10.2 ; C12.2 v2(112.14,14.1) ; R7.2 v2(111.56,23.46) R8.2 ; C6.2 104.09,14.99 v2(103.63,14.99) ; C39.2 104.85,82.12 v2(104.84,82.11) ; R53.2 v2(115.38,90.93) ; C16.2 93.59,21.59 v1(92.84,21.59) 92.58,21.59 ; R46.2 v2(89.15,84.96) ; C45.2 v2(112.14,81.41) ; TP42.1 v2(124.46,87) ; C13.2 v2(115.44,15.24) ; v1(97.16,37.72) 97.16,37.72 M2.2 ; R52.2 v2(115.38,87.5) ; R12.2 v2(115.44,23.62) ; C42.1 v2(89.15,87.5) ; R4.2 v2(107.7,14.22) ; TP21.1 v2(123.82,22.86) ; R64.2 v2(93.47,82.49) ; C9.1 v2(89.15,20.19) ; R44.2 v2(107.7,81.53) ; R23.2 v2(93.47,15.18) ; C19.2 v2(93.47,16.32) ; v2(112.14,87.12) C43.2 R83.2 v2(111,85.98) ; 96.65,41.01 95.88,41.01 ; C52.2 v2(93.47,83.63) ; 97.03,41.01 97.41,41.01 ; C46.2 v2(115.44,82.55) ; R5.2 v2(89.15,17.65)
  TOP w0.381: C10.2 v2(112.14,19.81)
  L3_SIG w0.254: v1(110.11,37.59) 108.25,35.74 106.5,35.74 v2(106.04,36.2) ; v1(110.1,104.9) 108.25,103.05 106.5,103.05 v2(106.04,103.5) ; v2(98.76,36.88) 97.99,36.88 v1(97.16,37.72) ; v1(97.16,105.03) 97.99,104.19 v2(98.76,104.19)
  L4_SIG w0.254: v2(124.46,87) 117.28,87 116.27,85.98 v2(111,85.98) ; v2(111,18.67) 119.63,18.67 v2(123.82,22.86)
  BOTTOM w0.254: v2(106.04,36.2) J7.4
  BOTTOM w0.381: v2(106.04,103.5) 105.74,103.5 105.36,103.89 J11.4
  vias: v1(1.52,11.43) v1(5.08,133.35) v1(5.08,128.27) v1(5.08,123.19) v1(5.08,118.11) v1(5.08,72.39) v1(5.08,67.31) v1(5.08,57.15) v1(5.08,52.07) v1(5.08,41.91) v1(5.08,36.83) v1(5.08,31.75) v1(5.08,26.67) v1(5.08,21.59) v1(5.08,11.43) v1(7.62,69.85) v1(7.62,54.61) v1(10.16,133.35) v1(10.16,128.27) v1(10.16,123.19) v1(10.16,118.11) v1(10.16,72.39) v1(10.16,52.07) v1(10.16,46.99) v1(10.16,41.91) v1(10.16,36.83) v1(10.16,31.75) v1(10.16,26.67) v1(10.16,21.59) v1(10.16,15.24) v1(10.16,11.43) v1(10.16,6.35) v1(12.7,69.85) v1(12.7,54.61) v1(15.24,133.35) v1(15.24,128.27) v1(15.24,123.19) v1(15.24,118.11) v1(15.24,67.31) v1(15.24,57.15) v1(15.24,52.07) v1(15.24,41.91) v1(15.24,36.83) v1(15.24,31.75) v1(15.24,26.67) v1(15.24,21.59) v1(15.24,11.43) v1(17.78,64.77) v1(17.78,59.69) v1(17.78,54.61) v1(20.32,118.11) v1(20.32,62.23) v1(20.32,57.15) v1(20.32,52.07) v1(20.32,36.83) v1(20.32,31.75) v1(20.32,26.67) v1(20.32,21.59) v1(20.32,15.24) v1(20.32,6.35) v1(22.73,128.91) v1(22.86,54.61) v1(23.37,129.79) v1(25.02,13.08) v1(25.15,129.79) v1(25.4,133.35) v1(25.4,118.11) v1(25.4,21.59) v1(25.4,11.43) v1(25.4,6.35) v1(25.91,13.84) v1(26.04,123.19) v1(27.69,13.84) v1(30.48,133.35) v1(30.48,128.27) v1(30.48,123.19) v1(30.48,118.11) v1(30.48,21.59) v1(30.48,16.51) v1(35.56,139.7) v1(35.56,133.35) v1(35.56,128.27) v1(35.56,123.19) v1(35.56,118.11) v1(35.56,21.59) v1(35.56,16.51) v1(35.56,11.43) v1(35.56,6.35) v1(40.64,133.35) v1(40.64,128.27) v1(40.64,123.19) v1(40.64,21.59) v1(40.64,16.51) v1(40.64,11.43) v1(40.64,6.35) v1(43.81,119.89) v1(43.81,117.98) v1(43.81,116.08) v1(43.81,94.11) v1(43.81,92.2) v1(43.81,90.3) v1(43.81,52.58) v1(43.81,50.67) v1(43.81,48.77) v1(43.81,26.8) v1(43.81,24.89) v1(43.81,22.99) v1(45.72,139.7) v1(45.72,133.35) v1(45.72,128.27) v1(45.72,123.19) v1(45.72,82.55) v1(45.72,77.47) v1(45.72,71.12) v1(45.72,66.04) v1(45.72,60.96) v1(45.72,55.88) v1(45.72,21.59) v1(45.72,16.51) v1(45.72,11.43) v1(45.72,6.35) v1(46.35,119.89) v1(46.35,117.98) v1(46.35,116.08) v1(46.35,94.11) v1(46.35,92.2) v1(46.35,90.3) v1(46.35,52.58) v1(46.35,50.67) v1(46.35,48.77) v1(46.35,26.8) v1(46.35,24.89) v1(46.35,22.99) v1(50.8,139.7) v1(50.8,133.35) v1(50.8,128.27) v1(50.8,123.19) v1(50.8,82.55) v1(50.8,77.47) v1(50.8,71.12) v1(50.8,66.04) v1(50.8,60.96) v1(50.8,55.88) v1(50.8,21.59) v1(50.8,16.51) v1(50.8,11.43) v1(50.8,6.35) v1(55.24,119.89) v1(55.24,117.98) v1(55.24,116.08) v1(55.24,94.11) v1(55.24,92.2) v1(55.24,90.3) v1(55.24,52.58) v1(55.24,50.67) v1(55.24,48.77) v1(55.24,26.8) v1(55.24,24.89) v1(55.24,22.99) v1(55.88,139.7) v1(55.88,133.35) v1(55.88,128.27) v1(55.88,123.19) v1(55.88,82.55) v1(55.88,77.47) v1(55.88,71.12) v1(55.88,66.04) v1(55.88,60.96) v1(55.88,55.88) v1(55.88,21.59) v1(55.88,16.51) v1(55.88,11.43) v1(55.88,6.35) v1(57.79,119.89) v1(57.79,117.98) v1(57.79,116.08) v1(57.79,94.11) v1(57.79,92.2) v1(57.79,90.3) v1(57.79,52.58) v1(57.79,50.67) v1(57.79,48.77) v1(57.79,26.8) v1(57.79,24.89) v1(57.79,22.99) v1(60.96,139.7) v1(60.96,133.35) v1(60.96,128.27) v1(60.96,123.19) v1(60.96,82.55) v1(60.96,77.47) v1(60.96,71.12) v1(60.96,66.04) v1(60.96,60.96) v1(60.96,55.88) v1(60.96,21.59) v1(60.96,16.51) v1(60.96,11.43) v1(60.96,6.35) v1(66.04,139.7) v1(66.04,133.35) v1(66.04,128.27) v1(66.04,123.19) v1(66.04,82.55) v1(66.04,77.47) v1(66.04,71.12) v1(66.04,66.04) v1(66.04,60.96) v1(66.04,55.88) v1(66.04,21.59) v1(66.04,16.51) v1(66.04,11.43) v1(66.04,6.35) v1(66.67,119.89) v1(66.67,117.98) v1(66.67,116.08) v1(66.67,94.11) v1(66.67,92.2) v1(66.67,90.3) v1(66.67,52.58) v1(66.67,50.67) v1(66.67,48.77) v1(66.67,26.8) v1(66.67,24.89) v1(66.67,22.99) v1(69.22,119.89) v1(69.22,117.98) v1(69.22,116.08) v1(69.22,94.11) v1(69.22,92.2) v1(69.22,90.3) v1(69.22,52.58) v1(69.22,50.67) v1(69.22,48.77) v1(69.22,26.8) v1(69.22,24.89) v1(69.22,22.99) v1(71.12,139.7) v1(71.12,133.35) v1(71.12,128.27) v1(71.12,123.19) v1(71.12,82.55) v1(71.12,77.47) v1(71.12,71.12) v1(71.12,66.04) v1(71.12,60.96) v1(71.12,55.88) v1(71.12,21.59) v1(71.12,16.51) v1(71.12,11.43) v1(71.12,6.35) v1(76.2,139.7) v1(76.2,133.35) v1(76.2,128.27) v1(76.2,123.19) v1(76.2,82.55) v1(76.2,77.47) v1(76.2,71.12) v1(76.2,66.04) v1(76.2,60.96) v1(76.2,55.88) v1(76.2,26.67) v1(76.2,21.59) v1(76.2,16.51) v1(76.2,11.43) v1(77.85,7.37) v1(77.98,17.27) v1(77.98,14.1) v1(77.98,10.79) v1(79.25,20.45) v1(79.5,17.27) v1(79.5,14.1) v1(79.5,10.79) v1(79.63,7.37) v1(80.39,63.63) v1(80.39,61.09) v1(80.39,58.55) v1(80.39,56.01) v1(80.39,53.47) v1(80.39,50.93) v1(80.39,26.92) v1(80.39,24.51) v1(80.39,22.23) v1(80.39,19.3) v1(80.77,66.29) v1(81.03,6.1) v1(81.28,139.7) v1(81.28,133.35) v1(81.28,128.27) v1(81.28,123.19) v1(81.28,92.71) v1(81.28,77.47) v1(81.28,71.12) v1(81.28,11.43) v1(81.79,50.8) v1(82.04,65.41) v1(82.04,21.21) v1(82.17,9.53) v1(82.68,68.2) v1(82.8,8) v1(83.19,63.75) v1(83.19,61.09) v1(83.19,58.55) v1(83.19,56.01) v1(83.19,53.47) v1(83.19,50.93) v1(83.19,48.51) v1(83.19,26.92) v1(83.19,24.51) v1(83.19,22.23) v1(83.95,19.3) v1(84.58,70.1) v1(84.84,65.91) v1(85.22,41.66) v1(85.22,41.15) v1(85.22,40.64) v1(85.22,38.35) v1(85.22,37.85) v1(85.22,37.34) v1(85.22,20.32) v1(85.22,9.53) v1(85.22,8) v1(85.34,108.97) v1(85.34,108.46) v1(85.34,107.95) v1(85.34,105.66) v1(85.34,105.16) v1(85.34,104.65) v1(85.98,17.27) v1(86.11,14.35) v1(86.36,139.7) v1(86.36,133.35) v1(86.36,128.27) v1(86.36,123.19) v1(86.36,92.71) v1(86.36,87.63) v1(86.36,77.47) v1(86.36,60.96) v1(86.36,55.88) v1(86.36,25.4) v1(86.36,11.43) v1(86.36,6.35) v1(86.49,72.01) v1(86.74,67.82) v1(87.12,109.98) v1(87.12,108.71) v1(87.12,107.44) v1(87.12,106.17) v1(87.12,103.63) v1(87.12,18.29) v1(87.25,104.9) v1(87.25,42.67) v1(87.25,41.4) v1(87.25,40.13) v1(87.25,38.86) v1(87.25,37.59) v1(87.25,36.32) v1(87.38,12.45) v1(87.88,10.16) v1(88.39,73.91) v1(88.52,8.76) v1(88.65,69.72) v1(88.9,134.62) v1(88.9,129.54) v1(88.9,124.46) v1(88.9,63.5) v1(88.9,58.42) v1(88.9,53.34) v1(89.92,10.03) v1(90.3,75.82) v1(90.55,71.63) v1(90.55,7.49) v1(91.44,139.7) v1(91.44,133.35) v1(91.44,66.04) v1(91.44,60.96) v1(91.82,10.29) v1(92.2,77.72) v1(92.46,73.53) v1(92.71,7.62) v1(92.84,89.53) v1(92.84,89.03) v1(92.84,22.1) v1(93.68,99.57) v1(93.68,32.26) v1(93.73,6.35) v1(93.98,134.62) v1(93.98,129.54) v1(93.98,68.58) v1(93.98,63.5) v1(94.23,77.6) v1(94.36,75.44) v1(95.5,10.29) v1(96.27,108.84) v1(96.27,77.34) v1(96.27,41.53) v1(96.52,139.7) v1(96.52,132.08) v1(96.52,71.12) v1(96.52,66.04) v1(96.52,60.96) v1(96.52,6.35) v1(96.77,9.27) v1(98.88,108.33) v1(98.88,107.31) v1(98.88,106.3) v1(98.88,41.02) v1(98.88,40.01) v1(98.88,38.99) v1(99.06,134.62) v1(99.06,129.54) v1(99.06,73.66) v1(99.06,68.58) v1(99.06,63.5) v1(101.6,132.08) v1(101.6,76.2) v1(101.6,71.12) v1(101.6,66.04) v1(101.6,60.96) v1(101.6,6.35) v1(102.36,91.69) v1(102.36,91.19) v1(102.36,90.68) v1(102.36,90.17) v1(102.36,89.66) v1(102.36,89.15) v1(102.36,88.65) v1(102.36,24.38) v1(102.36,23.88) v1(102.36,23.37) v1(102.36,22.86) v1(102.36,22.35) v1(102.36,21.84) v1(102.36,21.34) v1(102.49,108.33) v1(102.49,107.31) v1(102.49,106.3) v1(102.49,41.02) v1(102.49,40.01) v1(102.49,38.99) v1(102.87,91.69) v1(102.87,91.19) v1(102.87,90.68) v1(102.87,90.17) v1(102.87,89.66) v1(102.87,89.15) v1(102.87,88.65) v1(102.87,24.38) v1(102.87,23.88) v1(102.87,23.37) v1(102.87,22.86) v1(102.87,22.35) v1(102.87,21.84) v1(102.87,21.34) v1(103.38,91.69) v1(103.38,91.19) v1(103.38,90.68) v1(103.38,90.17) v1(103.38,89.66) v1(103.38,89.15) v1(103.38,88.65) v1(103.38,24.38) v1(103.38,23.88) v1(103.38,23.37) v1(103.38,22.86) v1(103.38,22.35) v1(103.38,21.84) v1(103.38,21.34) v1(104.14,134.62) v1(104.14,129.54) v1(104.14,63.5) v1(106.43,108.33) v1(106.43,107.31) v1(106.43,106.3) v1(106.43,41.02) v1(106.43,40.13) v1(106.43,38.99) v1(106.55,119.51) v1(106.55,116.21) v1(106.55,52.2) v1(106.55,48.9) v1(106.68,132.08) v1(106.68,76.2) v1(106.68,66.04) v1(106.68,60.96) v1(107.19,119.51) v1(107.19,116.21) v1(107.19,52.2) v1(107.19,48.9) v1(108.08,108.33) v1(108.08,107.31) v1(108.08,106.3) v1(108.08,41.02) v1(108.08,40.01) v1(108.08,38.99) v1(108.97,110.24) v1(108.97,42.93) v1(109.22,134.62) v1(109.22,129.54) v1(109.22,63.5) v1(109.98,109.03) v1(109.98,41.59) v1(110.1,102.87) v1(110.11,35.56) v1(111.76,132.08) v1(111.76,76.2) v1(111.76,71.12) v1(111.76,66.04) v1(111.76,60.96) v1(111.76,6.35) v1(114.3,134.62) v1(114.3,129.54) v1(114.3,73.66) v1(114.3,68.58) v1(114.3,63.5) v1(115.44,110.87) v1(115.44,109.35) v1(116.84,137.16) v1(116.84,132.08) v1(116.84,127) v1(116.84,121.92) v1(116.84,76.2) v1(116.84,71.12) v1(116.84,66.04) v1(116.84,60.96) v1(116.84,55.88) v1(116.84,6.35) v1(119,109.98) v1(119,108.84) v1(119,107.44) v1(119,106.17) v1(119,104.9) v1(119,103.63) v1(119.13,42.67) v1(119.13,41.4) v1(119.13,40.13) v1(119.13,38.86) v1(119.13,37.59) v1(119.13,36.32) v1(119.38,129.54) v1(119.38,124.46) v1(119.38,119.38) v1(119.38,68.58) v1(119.38,63.5) v1(119.38,58.42) v1(119.38,53.34) v1(120.9,108.97) v1(120.9,108.46) v1(120.9,107.95) v1(120.9,105.66) v1(120.9,105.16) v1(120.9,104.65) v1(120.9,41.66) v1(120.9,41.15) v1(120.9,40.64) v1(120.9,38.35) v1(120.9,37.85) v1(120.9,37.34) v1(121.92,137.16) v1(121.92,133.35) v1(121.92,76.2) v1(121.92,71.12) v1(121.92,11.43) v1(124.46,130.21) v1(124.46,128.68) v1(124.46,127.16) v1(124.46,62.9) v1(124.46,61.37) v1(124.46,59.85) v1(127,137.16) v1(127,133.35) v1(127,76.2) v1(127,71.12) v1(127,66.04) v1(127,21.59) v1(127,11.43) v1(128.27,130.21) v1(128.27,128.68) v1(128.27,127.16) v1(128.27,62.9) v1(128.27,61.37) v1(128.27,59.85) v1(132.08,137.16) v1(132.08,133.35) v1(132.08,130.21) v1(132.08,128.68) v1(132.08,127.16) v1(132.08,81.28) v1(132.08,76.2) v1(132.08,71.12) v1(132.08,66.04) v1(132.08,62.9) v1(132.08,61.37) v1(132.08,59.85) v1(132.08,21.59) v1(132.08,11.43) v1(135.89,130.21) v1(135.89,128.68) v1(135.89,127.16) v1(135.89,62.9) v1(135.89,61.37) v1(135.89,59.85) v1(137.16,137.16) v1(137.16,133.35) v1(137.16,76.2) v1(137.16,71.12) v1(137.16,66.04) v1(137.16,21.59) v1(137.16,11.43) v1(142.24,137.16) v1(142.24,133.35) v1(142.24,128.27) v1(142.24,123.19) v1(142.24,118.11) v1(142.24,76.2) v1(142.24,71.12) v1(142.24,66.04) v1(142.24,60.96) v1(142.24,55.88) v1(142.24,50.8) v1(142.24,16.51) v1(142.24,11.43) v1(147.32,128.27) v1(147.32,123.19) v1(147.32,119.89) v1(147.32,118.36) v1(147.32,116.84) v1(147.32,98.43) v1(147.32,96.9) v1(147.32,95.38) v1(147.32,82.55) v1(147.32,76.2) v1(147.32,71.12) v1(147.32,66.04) v1(147.32,60.96) v1(147.32,55.88) v1(147.32,52.45) v1(147.32,50.93) v1(147.32,49.4) v1(147.32,31.12) v1(147.32,29.59) v1(147.32,28.07) v1(147.32,21.59) v1(147.32,16.51) v1(147.32,11.43) v1(149.86,119.89) v1(149.86,118.36) v1(149.86,116.84) v1(149.86,98.43) v1(149.86,96.9) v1(149.86,95.38) v1(149.86,52.45) v1(149.86,50.93) v1(149.86,49.4) v1(149.86,31.12) v1(149.86,29.59) v1(149.86,28.07) v1(152.4,128.27) v1(152.4,26.67) v1(152.4,21.59) v1(152.4,16.51) v1(152.4,11.43) v1(157.48,137.16) v1(157.48,133.35) v1(157.48,128.27) v1(157.48,123.19) v1(157.48,118.11) v1(157.48,31.75) v1(157.48,26.67) v1(157.48,21.59) v1(157.48,16.51) v1(157.48,11.43) v1(157.48,6.35) v1(162.56,128.27) v1(162.56,123.19) v1(162.56,118.11) v1(162.56,31.75) v1(162.56,26.67) v1(162.56,21.59) v1(162.56,16.51) v1(162.56,11.43) v1(167.64,137.16) v1(167.64,133.35) v1(167.64,128.27) v1(167.64,123.19) v1(167.64,118.11) v1(167.64,62.23) v1(167.64,57.15) v1(167.64,52.07) v1(167.64,41.91) v1(167.64,31.75) v1(167.64,26.67) v1(167.64,21.59) v1(167.64,16.51) v1(167.64,11.43) v1(167.64,6.35) v1(170.18,64.77) v1(170.18,59.69) v1(170.18,54.61) v1(172.72,133.35) v1(172.72,128.27) v1(172.72,123.19) v1(172.72,118.11) v1(172.72,67.31) v1(172.72,62.23) v1(172.72,57.15) v1(172.72,52.07) v1(172.72,36.83) v1(172.72,31.75) v1(172.72,26.67) v1(172.72,21.59) v1(172.72,16.51) v1(172.72,11.43) v1(172.72,6.35) v1(175.26,69.85) v1(175.26,54.61) v1(177.8,128.27) v1(177.8,123.19) v1(177.8,118.11) v1(177.8,72.39) v1(177.8,57.15) v1(177.8,52.07) v1(177.8,46.99) v1(177.8,41.91) v1(177.8,36.83) v1(177.8,31.75) v1(177.8,26.67) v1(177.8,21.59) v1(177.8,16.51) v1(177.8,11.43) v1(180.34,69.85) v1(180.34,54.61) v1(182.88,133.35) v1(182.88,128.27) v1(182.88,123.19) v1(182.88,118.11) v1(182.88,72.39) v1(182.88,52.07) v1(182.88,41.91) v1(182.88,36.83) v1(182.88,31.75) v1(182.88,26.67) v1(182.88,16.51) v1(182.88,11.43) v1(185.42,69.85) v1(185.42,54.61) v1(188.98,16.51) v1(188.98,11.43) v2(81.79,27.05) v2(88.39,109.98) v2(88.39,108.71) v2(88.39,107.44) v2(88.39,106.17) v2(88.39,104.9) v2(88.39,103.63) v2(88.39,42.67) v2(88.39,41.4) v2(88.39,40.13) v2(88.39,38.86) v2(88.39,37.59) v2(88.39,36.32) v2(93.47,86.88) v2(93.47,86.5) v2(93.47,19.57) v2(93.47,19.19) v2(95.88,108.35) v2(95.88,107.31) v2(95.88,106.31) v2(95.88,41.04) v2(95.88,40) v2(95.88,39) v2(96.27,108.35) v2(96.27,107.31) v2(96.27,106.31) v2(96.27,41.04) v2(96.27,40) v2(96.27,39) v2(96.65,108.35) v2(96.65,107.31) v2(96.65,106.31) v2(96.65,41.04) v2(96.65,40) v2(96.65,39) v2(97.03,108.35) v2(97.03,107.31) v2(97.03,106.31) v2(97.03,41.04) v2(97.03,40) v2(97.03,39) v2(97.41,108.35) v2(97.41,107.31) v2(97.41,106.31) v2(97.41,41.04) v2(97.41,40) v2(97.41,39) v2(108.84,108.35) v2(108.84,107.31) v2(108.84,106.31) v2(108.84,41.04) v2(108.86,40) v2(108.86,39) v2(109.19,41.04) v2(109.22,108.35) v2(109.22,107.31) v2(109.22,106.31) v2(109.22,40) v2(109.22,39) v2(109.58,41.04) v2(109.6,108.35) v2(109.6,40) v2(109.6,39) v2(109.98,108.35) v2(109.96,41.04) v2(109.98,40) v2(109.98,39) v2(110.36,108.35) v2(110.34,41.04) v2(110.36,40) v2(110.36,39) v2(117.86,109.98) v2(117.86,108.71) v2(117.86,107.44) v2(117.86,106.17) v2(117.86,104.9) v2(117.86,103.63) v2(117.86,42.67) v2(117.86,41.53) v2(117.86,40.51) v2(117.86,39.5) v2(117.86,38.48) v2(117.86,37.47) v2(117.86,36.32) v3(1.65,128.27) v3(1.65,123.19) v3(1.65,118.11) v3(1.65,113.03) v3(1.65,107.95) v3(1.65,102.87) v3(1.65,97.79) v3(1.65,92.71) v3(1.65,87.63) v3(1.65,82.55) v3(1.65,77.47) v3(1.65,72.39) v3(1.65,67.31) v3(1.65,62.23) v3(1.65,57.15) v3(1.65,52.07) v3(1.65,46.99) v3(1.65,41.91) v3(1.65,36.83) v3(1.65,31.75) v3(1.65,26.67) v3(1.65,21.59) v3(1.65,16.51) v3(10.16,143.13) v3(10.16,1.65) v3(15.24,143.13) v3(15.24,1.65) v3(20.32,143.13) v3(20.32,1.65) v3(25.4,143.13) v3(25.4,1.65) v3(30.48,143.13) v3(30.48,1.65) v3(35.56,143.13) v3(35.56,1.65) v3(40.64,143.13) v3(40.64,1.65) v3(45.72,143.13) v3(45.72,1.65) v3(50.8,143.13) v3(50.8,1.65) v3(55.88,143.13) v3(55.88,1.65) v3(60.96,143.13) v3(60.96,1.65) v3(66.04,143.13) v3(66.04,1.65) v3(71.12,143.13) v3(71.12,1.65) v3(76.2,143.13) v3(76.2,1.65) v3(81.28,143.13) v3(81.28,1.65) v3(86.36,143.13) v3(86.36,1.65) v3(91.44,143.13) v3(91.44,1.65) v3(96.52,143.13) v3(96.52,1.65) v3(101.6,143.13) v3(101.6,1.65) v3(106.68,143.13) v3(106.68,1.65) v3(111.76,143.13) v3(111.76,1.65) v3(116.84,143.13) v3(116.84,1.65) v3(121.92,143.13) v3(121.92,1.65) v3(127,143.13) v3(127,1.65) v3(132.08,143.13) v3(132.08,1.65) v3(137.16,143.13) v3(137.16,1.65) v3(142.24,143.13) v3(142.24,1.65) v3(147.32,143.13) v3(147.32,1.65) v3(152.4,143.13) v3(152.4,1.65) v3(157.48,143.13) v3(157.48,1.65) v3(162.56,143.13) v3(162.56,1.65) v3(167.64,143.13) v3(167.64,1.65) v3(172.72,143.13) v3(172.72,1.65) v3(177.8,143.13) v3(177.8,1.65) v3(188.85,133.35) v3(188.85,128.27) v3(188.85,123.19) v3(188.85,118.11) v3(188.85,113.03) v3(188.85,107.95) v3(188.85,102.87) v3(188.85,97.79) v3(188.85,92.71) v3(188.85,87.63) v3(188.85,82.55) v3(188.85,77.47) v3(188.85,72.39) v3(188.85,67.31) v3(188.85,62.23) v3(188.85,57.15) v3(188.85,52.07) v3(188.85,46.99) v3(188.85,41.91) v3(188.85,36.83) v3(188.85,31.75) v3(188.85,26.67) v3(188.85,21.59)
